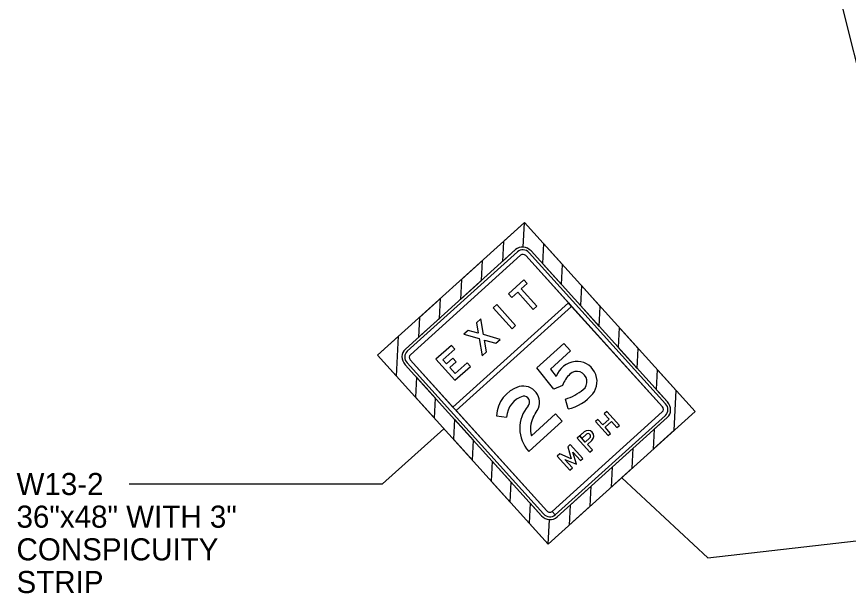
# Model space of a CAD drawing. Extents: x 571683 to 574814, y 1530838 to 1532905.
# Drawn here: x 572370 to 573075, y 1531892 to 1532381 of the extents above; entities that cross this region are included whole.
import ezdxf

# ---------------------------------------------------------------- set-up
doc = ezdxf.new("R2010")
doc.units = 0
for name, color, linetype in [('SignDetail', 7, 'Continuous'), ('SignPanel', 7, 'Continuous'), ('TextLabel', 7, 'Continuous')]:
    doc.layers.add(name, color=color, linetype=linetype)

msp = doc.modelspace()

# ---------------------------------------------------------------- linework, layer by layer
at = {"layer": 'SignDetail'}
for p, q in [((573132.85, 1532137.75), (572992.32, 1532700.81)), ((572465, 1531984.47), (572680, 1531984.47)), ((572955.73, 1531921.8), (573341.41, 1531966.12))]:
    msp.add_line(p, q, dxfattribs=at)
at = {"layer": 'SignPanel'}
for p, q in [((572792.72, 1532183.38), (572699.24, 1532098.9)), ((572794.33, 1532181.6), (572700.85, 1532097.12)), ((572794.33, 1532181.6), (572700.85, 1532097.12)), ((572794.33, 1532181.6), (572700.85, 1532097.12)), ((572794.33, 1532181.6), (572700.85, 1532097.12)), ((572797.01, 1532178.63), (572703.53, 1532094.15)), ((572797.01, 1532178.63), (572703.53, 1532094.15)), ((572797.01, 1532178.63), (572703.53, 1532094.15)), ((572703.53, 1532094.15), (572797.01, 1532178.63)), ((572920.02, 1532052.6), (572804.16, 1532180.78)), ((572920.02, 1532052.6), (572804.16, 1532180.78)), ((572920.02, 1532052.6), (572804.16, 1532180.78)), ((572920.02, 1532052.6), (572804.16, 1532180.78)), ((572921.68, 1532054.1), (572805.83, 1532182.29)), ((572917.23, 1532050.08), (572801.38, 1532178.27)), ((572917.23, 1532050.08), (572801.38, 1532178.27)), ((572917.23, 1532050.08), (572801.38, 1532178.27)), ((572801.38, 1532178.27), (572837.59, 1532138.21)), ((572837.59, 1532138.21), (572739.66, 1532049.7)), ((572837.59, 1532138.21), (572739.66, 1532049.7)), ((572837.59, 1532138.21), (572739.66, 1532049.7)), ((572837.59, 1532138.21), (572739.66, 1532049.7)), ((572840.27, 1532135.24), (572837.59, 1532138.21)), ((572840.27, 1532135.24), (572837.59, 1532138.21)), ((572840.27, 1532135.24), (572837.59, 1532138.21)), ((572840.27, 1532135.24), (572837.59, 1532138.21)), ((572837.59, 1532138.21), (572840.27, 1532135.24)), ((572742.34, 1532046.74), (572840.27, 1532135.24)), ((572742.34, 1532046.74), (572840.27, 1532135.24)), ((572742.34, 1532046.74), (572840.27, 1532135.24)), ((572742.34, 1532046.74), (572840.27, 1532135.24)), ((572840.27, 1532135.24), (572917.23, 1532050.08)), ((572693.42, 1532109.81), (572675.62, 1532093.72)), ((572700.67, 1532087.25), (572816.53, 1531959.06)), ((572700.67, 1532087.25), (572816.53, 1531959.06)), ((572700.67, 1532087.25), (572816.53, 1531959.06)), ((572700.67, 1532087.25), (572816.53, 1531959.06)), ((572703.45, 1532089.76), (572819.31, 1531961.58)), ((572703.45, 1532089.76), (572819.31, 1531961.58)), ((572703.45, 1532089.76), (572819.31, 1531961.58)), ((572739.66, 1532049.7), (572703.45, 1532089.76)), ((572699, 1532085.74), (572814.86, 1531957.55)), ((572827.12, 1532075.72), (572827.12, 1532075.72)), ((572837.21, 1532048.12), (572835.02, 1532056.58)), ((572837.21, 1532048.12), (572835.02, 1532056.58)), ((572835.02, 1532056.58), (572835.02, 1532056.58)), ((572837.21, 1532048.12), (572835.02, 1532056.58)), ((572835.02, 1532056.58), (572835.02, 1532056.58)), ((572739.66, 1532049.7), (572742.34, 1532046.74)), ((572739.66, 1532049.7), (572742.34, 1532046.74)), ((572739.66, 1532049.7), (572742.34, 1532046.74)), ((572739.66, 1532049.7), (572742.34, 1532046.74)), ((572742.34, 1532046.74), (572739.66, 1532049.7)), ((572819.31, 1531961.58), (572742.34, 1532046.74)), ((572823.68, 1531961.21), (572917.15, 1532045.7)), ((572823.7, 1531961.24), (572917.15, 1532045.7)), ((572823.7, 1531961.24), (572917.15, 1532045.7)), ((572917.15, 1532045.7), (572823.7, 1531961.24)), ((572776.48, 1532042.34), (572785.11, 1532041.3)), ((572776.48, 1532042.34), (572785.11, 1532041.3)), ((572776.48, 1532042.34), (572785.11, 1532041.3)), ((572826.36, 1531958.25), (572919.84, 1532042.73)), ((572826.39, 1531958.27), (572919.84, 1532042.73)), ((572826.39, 1531958.27), (572919.84, 1532042.73)), ((572826.39, 1531958.27), (572919.84, 1532042.73)), ((572827.97, 1531956.47), (572921.44, 1532040.95)), ((572680, 1531984.47), (572731.94, 1532031.4)), ((572855.69, 1532023.56), (572851.83, 1532020.08)), ((572853.71, 1532018), (572857.55, 1532021.48)), ((572882.75, 1531989.8), (572955.73, 1531921.8)), ((572826.36, 1531958.25), (572823.68, 1531961.21)), ((572826.36, 1531958.25), (572823.68, 1531961.21)), ((572826.36, 1531958.25), (572823.68, 1531961.21)), ((572823.7, 1531961.24), (572826.39, 1531958.27)), ((572823.7, 1531961.24), (572826.39, 1531958.27)), ((572823.7, 1531961.24), (572826.39, 1531958.27))]:
    msp.add_line(p, q, dxfattribs=at)
for points in [[(572820.44, 1531933.48), (572945.07, 1532046.13), (572800.25, 1532206.36), (572675.62, 1532093.72), (572820.44, 1531933.48)], [(572799.2, 1532185.57), (572800.25, 1532206.36), (572782.45, 1532190.27), (572781.59, 1532173.32), (572792.72, 1532183.38)], [(572815.49, 1532171.61), (572831.58, 1532153.8), (572832.44, 1532170.75), (572816.34, 1532188.56), (572815.49, 1532171.61)], [(572699.24, 1532098.9), (572792.72, 1532183.38)], [(572805.83, 1532182.29), (572921.68, 1532054.1)], [(572745.98, 1532141.14), (572763.78, 1532157.23), (572764.64, 1532174.18), (572746.84, 1532158.08), (572745.98, 1532141.14)], [(572863.76, 1532118.19), (572864.62, 1532135.14), (572848.53, 1532152.95), (572847.67, 1532136), (572863.76, 1532118.19)], [(572710.37, 1532108.95), (572728.17, 1532125.04), (572729.03, 1532141.99), (572711.22, 1532125.9), (572710.37, 1532108.95)], [(572895.95, 1532082.58), (572896.81, 1532099.53), (572880.71, 1532117.33), (572879.86, 1532100.39), (572895.95, 1532082.58)], [(572693.42, 1532109.81), (572675.62, 1532093.72), (572691.71, 1532075.92), (572693.42, 1532109.81)], [(572832.62, 1532068.15), (572825.06, 1532064.87), (572810.91, 1532083.09), (572833.74, 1532103.73), (572839.38, 1532097.5), (572822.23, 1532082.01), (572827.12, 1532075.72)], [(572832.62, 1532068.15), (572825.06, 1532064.87), (572810.91, 1532083.09), (572833.74, 1532103.73), (572839.38, 1532097.5), (572822.23, 1532082.01), (572827.12, 1532075.72)], [(572832.62, 1532068.15), (572825.06, 1532064.87), (572810.91, 1532083.09), (572833.74, 1532103.73), (572839.38, 1532097.5), (572822.23, 1532082.01), (572827.12, 1532075.72)], [(572814.86, 1531957.55), (572699, 1532085.74)], [(572921.44, 1532040.95), (572910.33, 1532030.9), (572909.47, 1532013.95), (572927.28, 1532030.05), (572928.99, 1532063.92), (572912.9, 1532081.72), (572912.04, 1532064.77)], [(572707.8, 1532058.11), (572723.89, 1532040.31), (572724.75, 1532057.26), (572708.65, 1532075.06), (572707.8, 1532058.11)], [(572912.04, 1532064.77), (572921.68, 1532054.1)], [(572756.93, 1532021.65), (572740.84, 1532039.45), (572739.98, 1532022.5), (572756.08, 1532004.7), (572756.93, 1532021.65)], [(572803.87, 1532012.04), (572832.28, 1532037.71), (572826.65, 1532043.95), (572806.12, 1532025.39)], [(572803.87, 1532012.04), (572832.28, 1532037.71), (572826.65, 1532043.95), (572806.12, 1532025.39)], [(572803.87, 1532012.04), (572832.28, 1532037.71), (572826.65, 1532043.95), (572806.12, 1532025.39)], [(572921.44, 1532040.95), (572827.97, 1531956.47), (572827.97, 1531956.47)], [(572850.98, 1532028.75), (572845.09, 1532023.42), (572855.82, 1532011.55), (572857.87, 1532013.4), (572853.71, 1532018)], [(572847.14, 1532025.27), (572845.09, 1532023.42), (572855.82, 1532011.55), (572857.87, 1532013.4), (572853.71, 1532018), (572857.55, 1532021.48)], [(572847.14, 1532025.27), (572845.09, 1532023.42), (572855.82, 1532011.55), (572857.87, 1532013.4), (572853.71, 1532018), (572857.55, 1532021.48)], [(572850.98, 1532028.75), (572847.14, 1532025.27), (572849.02, 1532023.2), (572852.87, 1532026.68)], [(572850.98, 1532028.75), (572847.14, 1532025.27), (572849.02, 1532023.2), (572852.87, 1532026.68)], [(572855.69, 1532023.56), (572851.83, 1532020.08), (572847.14, 1532025.27)], [(572855.69, 1532023.56), (572851.83, 1532020.08), (572847.14, 1532025.27)], [(572851.83, 1532020.08), (572849.02, 1532023.2), (572852.87, 1532026.68)], [(572891.67, 1531997.86), (572892.52, 1532014.81), (572874.72, 1531998.72), (572873.86, 1531981.77), (572891.67, 1531997.86)], [(572789.12, 1531986.03), (572773.02, 1532003.84), (572772.17, 1531986.89), (572788.26, 1531969.09), (572789.12, 1531986.03)], [(572856.06, 1531965.68), (572856.91, 1531982.63), (572839.11, 1531966.53), (572838.25, 1531949.59), (572856.06, 1531965.68)], [(572814.86, 1531957.55), (572805.21, 1531968.23), (572804.35, 1531951.28), (572820.44, 1531933.47), (572821.5, 1531954.28)]]:
    msp.add_lwpolyline(points, dxfattribs=at)
for points in [[(572789.53, 1532142.75), (572794.53, 1532147.27), (572807.8, 1532132.58), (572810.87, 1532135.35), (572797.6, 1532150.04), (572802.59, 1532154.56), (572799.78, 1532157.67), (572786.71, 1532145.87)], [(572789.53, 1532142.75), (572794.53, 1532147.27), (572807.8, 1532132.58), (572810.87, 1532135.35), (572797.6, 1532150.04), (572802.59, 1532154.56), (572799.78, 1532157.67), (572786.71, 1532145.87)], [(572789.53, 1532142.75), (572794.53, 1532147.27), (572807.8, 1532132.58), (572810.87, 1532135.35), (572797.6, 1532150.04), (572802.59, 1532154.56), (572799.78, 1532157.67), (572786.71, 1532145.87)], [(572789.73, 1532116.24), (572773.64, 1532134.05), (572776.71, 1532136.82), (572792.8, 1532119.02)], [(572789.73, 1532116.24), (572773.64, 1532134.05), (572776.71, 1532136.82), (572792.8, 1532119.02)], [(572789.73, 1532116.24), (572773.64, 1532134.05), (572776.71, 1532136.82), (572792.8, 1532119.02)], [(572764.38, 1532093.33), (572768.02, 1532096.63), (572766.27, 1532106.67), (572776.08, 1532103.91), (572779.73, 1532107.2), (572765.47, 1532111.21), (572763.14, 1532124.56), (572759.5, 1532121.27), (572761.04, 1532112.46), (572752.42, 1532114.88), (572748.78, 1532111.59), (572761.83, 1532107.92)], [(572764.38, 1532093.33), (572768.02, 1532096.63), (572766.27, 1532106.67), (572776.08, 1532103.91), (572779.73, 1532107.2), (572765.47, 1532111.21), (572763.14, 1532124.56), (572759.5, 1532121.27), (572761.04, 1532112.46), (572752.42, 1532114.88), (572748.78, 1532111.59), (572761.83, 1532107.92)], [(572764.38, 1532093.33), (572768.02, 1532096.63), (572766.27, 1532106.67), (572776.08, 1532103.91), (572779.73, 1532107.2), (572765.47, 1532111.21), (572763.14, 1532124.56), (572759.5, 1532121.27), (572761.04, 1532112.46), (572752.42, 1532114.88), (572748.78, 1532111.59), (572761.83, 1532107.92)], [(572751.56, 1532087.41), (572741.56, 1532078.37), (572737.07, 1532083.34), (572742.37, 1532088.13), (572739.56, 1532091.25), (572734.26, 1532086.46), (572731.1, 1532089.95), (572741.1, 1532098.98), (572738.28, 1532102.1), (572725.22, 1532090.29), (572741.31, 1532072.48), (572754.38, 1532084.29)], [(572751.56, 1532087.41), (572741.56, 1532078.37), (572737.07, 1532083.34), (572742.37, 1532088.13), (572739.56, 1532091.25), (572734.26, 1532086.46), (572731.1, 1532089.95), (572741.1, 1532098.98), (572738.28, 1532102.1), (572725.22, 1532090.29), (572741.31, 1532072.48), (572754.38, 1532084.29)], [(572751.56, 1532087.41), (572741.56, 1532078.37), (572737.07, 1532083.34), (572742.37, 1532088.13), (572739.56, 1532091.25), (572734.26, 1532086.46), (572731.1, 1532089.95), (572741.1, 1532098.98), (572738.28, 1532102.1), (572725.22, 1532090.29), (572741.31, 1532072.48), (572754.38, 1532084.29)], [(572872.21, 1532039.5), (572866.83, 1532034.64), (572862.63, 1532039.28), (572860.59, 1532037.43), (572871.32, 1532025.56), (572873.36, 1532027.41), (572868.7, 1532032.56), (572874.08, 1532037.42), (572878.74, 1532032.27), (572880.79, 1532034.12), (572870.06, 1532045.99), (572868.01, 1532044.14)], [(572872.21, 1532039.5), (572866.83, 1532034.64), (572862.63, 1532039.28), (572860.59, 1532037.43), (572871.32, 1532025.56), (572873.36, 1532027.41), (572868.7, 1532032.56), (572874.08, 1532037.42), (572878.74, 1532032.27), (572880.79, 1532034.12), (572870.06, 1532045.99), (572868.01, 1532044.14)], [(572872.21, 1532039.5), (572866.83, 1532034.64), (572862.63, 1532039.28), (572860.59, 1532037.43), (572871.32, 1532025.56), (572873.36, 1532027.41), (572868.7, 1532032.56), (572874.08, 1532037.42), (572878.74, 1532032.27), (572880.79, 1532034.12), (572870.06, 1532045.99), (572868.01, 1532044.14)], [(572834.45, 1532005.23), (572844.33, 1532001.17), (572841.29, 1532011.41), (572847.75, 1532004.26), (572849.8, 1532006.11), (572839.07, 1532017.98), (572837.01, 1532016.11), (572840.03, 1532005.93), (572830.2, 1532009.97), (572828.14, 1532008.1), (572838.87, 1531996.23), (572840.91, 1531998.08)], [(572834.45, 1532005.23), (572844.33, 1532001.17), (572841.29, 1532011.41), (572847.75, 1532004.26), (572849.8, 1532006.11), (572839.07, 1532017.98), (572837.01, 1532016.11), (572840.03, 1532005.93), (572830.2, 1532009.97), (572828.14, 1532008.1), (572838.87, 1531996.23), (572840.91, 1531998.08)], [(572834.45, 1532005.23), (572844.33, 1532001.17), (572841.29, 1532011.41), (572847.75, 1532004.26), (572849.8, 1532006.11), (572839.07, 1532017.98), (572837.01, 1532016.11), (572840.03, 1532005.93), (572830.2, 1532009.97), (572828.14, 1532008.1), (572838.87, 1531996.23), (572840.91, 1531998.08)]]:
    msp.add_lwpolyline(points, close=True, dxfattribs=at)
for centre, major_axis, ratio, start_param, end_param in [((572799.15, 1532176.26), (-6.44, 7.12), 0.937555, 4.712389, 6.283185), ((572799.15, 1532176.26), (-6.44, 7.12), 0.937555, 4.712389, 6.283185), ((572799.15, 1532176.26), (-6.44, 7.12), 0.937555, 5.51114, 6.283185), ((572799.15, 1532176.26), (-4.83, 5.34), 0.937555, 4.712389, 6.283185), ((572799.15, 1532176.26), (-4.83, 5.34), 0.937555, 4.712389, 6.283185), ((572799.15, 1532176.26), (-4.83, 5.34), 0.937555, 4.712389, 6.283185), ((572799.15, 1532176.26), (-4.83, 5.34), 0.937555, 4.712389, 6.283185), ((572799.15, 1532176.26), (-2.15, 2.37), 0.937555, 4.712389, 6.283185), ((572799.15, 1532176.26), (-2.15, 2.37), 0.937555, 4.712389, 6.283185), ((572799.15, 1532176.26), (-2.15, 2.37), 0.937555, 4.712389, 6.283185), ((572799.15, 1532176.26), (-2.15, 2.37), 0.937555, 4.712389, 6.283185), ((572705.68, 1532091.78), (-6.44, 7.12), 0.937555, 0, 1.570796), ((572705.68, 1532091.78), (-6.44, 7.12), 0.937555, 0, 1.570796), ((572705.68, 1532091.78), (-4.83, 5.34), 0.937555, 0, 1.570796), ((572705.68, 1532091.78), (-4.83, 5.34), 0.937555, 0, 1.570796), ((572705.68, 1532091.78), (-4.83, 5.34), 0.937555, 0, 1.570796), ((572705.68, 1532091.78), (-4.83, 5.34), 0.937555, 0, 1.570796), ((572705.68, 1532091.78), (-2.15, 2.37), 0.937555, 0, 1.570796), ((572705.68, 1532091.78), (-2.15, 2.37), 0.937555, 0, 1.570796), ((572705.68, 1532091.78), (-2.15, 2.37), 0.937555, 0, 1.570796), ((572705.68, 1532091.78), (-2.15, 2.37), 0.937555, 0, 1.570796), ((572845.85, 1532068.72), (-13.45, 14.88), 0.985, 5.674797, 6.76791), ((572845.85, 1532068.72), (-13.45, 14.88), 0.985, 5.674797, 6.76791), ((572845.85, 1532068.72), (-13.45, 14.88), 0.985, 5.674797, 6.76791), ((572844.97, 1532071.68), (-11.4, 12.62), 0.985, 3.29706, 5.646286), ((572844.97, 1532071.68), (-11.4, 12.62), 0.985, 3.29706, 5.646286), ((572844.97, 1532071.68), (-11.4, 12.62), 0.985, 3.29706, 5.646286), ((572844.8, 1532071.44), (-5.78, 6.39), 0.985, 3.050128, 6.31212), ((572844.8, 1532071.44), (-5.78, 6.39), 0.985, 3.050128, 6.31212), ((572844.8, 1532071.44), (-5.78, 6.39), 0.985, 3.050128, 6.31212), ((572856.17, 1532059.3), (-16.92, 18.72), 0.985, 0.021733, 0.482857), ((572856.17, 1532059.3), (-16.92, 18.72), 0.985, 0.021733, 0.482857), ((572856.17, 1532059.3), (-16.92, 18.72), 0.985, 0.021733, 0.482857), ((572804.71, 1532040.14), (-19.12, 21.16), 0.985, 5.861869, 7.048709), ((572804.71, 1532040.14), (-19.12, 21.16), 0.985, 5.861869, 7.048709), ((572804.71, 1532040.14), (-19.12, 21.16), 0.985, 5.861869, 7.048709), ((572799.39, 1532053.96), (-9.2, 10.18), 0.985, 3.445077, 5.80948), ((572799.39, 1532053.96), (-9.2, 10.18), 0.985, 3.445077, 5.80948), ((572799.39, 1532053.96), (-9.2, 10.18), 0.985, 3.445077, 5.80948), ((572804.84, 1532039.84), (-13.36, 14.78), 0.985, 5.833638, 7.052577), ((572804.84, 1532039.84), (-13.36, 14.78), 0.985, 5.833638, 7.052577), ((572804.84, 1532039.84), (-13.36, 14.78), 0.985, 5.833638, 7.052577), ((572799.94, 1532054.14), (-3.23, 3.58), 0.985, 3.193411, 5.709913), ((572799.94, 1532054.14), (-3.23, 3.58), 0.985, 3.193411, 5.709913), ((572799.94, 1532054.14), (-3.23, 3.58), 0.985, 3.193411, 5.709913), ((572822.39, 1532097.65), (-28.89, 31.97), 0.985, 2.699218, 3.100889), ((572822.39, 1532097.65), (-28.89, 31.97), 0.985, 2.699218, 3.100889), ((572822.39, 1532097.65), (-28.89, 31.97), 0.985, 2.699218, 3.100889), ((572828.72, 1532085.13), (-25.55, 28.27), 0.985, 2.625811, 3.292278), ((572828.72, 1532085.13), (-25.55, 28.27), 0.985, 2.625811, 3.292278), ((572828.72, 1532085.13), (-25.55, 28.27), 0.985, 2.625811, 3.292278), ((572915.01, 1532048.07), (-4.83, 5.34), 0.937555, 3.141593, 4.712389), ((572915.01, 1532048.07), (-4.83, 5.34), 0.937555, 3.141593, 4.712389), ((572915.01, 1532048.07), (-4.83, 5.34), 0.937555, 3.141593, 4.712389), ((572915.01, 1532048.07), (-4.83, 5.34), 0.937555, 3.141593, 4.712389), ((572915.01, 1532048.07), (-6.44, 7.12), 0.937555, 3.141593, 4.712389), ((572915.01, 1532048.07), (-6.44, 7.12), 0.937555, 3.141593, 4.712389), ((572915.01, 1532048.07), (-6.44, 7.12), 0.937555, 3.141593, 4.712389), ((572825.61, 1532031.35), (-19.79, 21.9), 0.985, 0.121378, 1.562513), ((572825.61, 1532031.35), (-19.79, 21.9), 0.985, 0.121378, 1.562513), ((572825.61, 1532031.35), (-19.79, 21.9), 0.985, 0.121378, 1.562513), ((572673.45, 1532124.62), (-106.18, 117.48), 0.985, 3.423454, 3.46857), ((572673.45, 1532124.62), (-106.18, 117.48), 0.985, 3.423454, 3.46857), ((572673.45, 1532124.62), (-106.18, 117.48), 0.985, 3.423454, 3.46857), ((572915.01, 1532048.07), (-2.15, 2.37), 0.937555, 3.141593, 4.712389), ((572915.01, 1532048.07), (-2.15, 2.37), 0.937555, 3.141593, 4.712389), ((572915.01, 1532048.07), (-2.15, 2.37), 0.937555, 3.141593, 4.712389), ((572915.01, 1532048.07), (-2.15, 2.37), 0.937555, 3.141593, 4.712389), ((572826.56, 1532030.91), (-14.37, 15.9), 0.985, 0.357174, 1.105945), ((572826.56, 1532030.91), (-14.37, 15.9), 0.985, 0.357174, 1.105945), ((572826.56, 1532030.91), (-14.37, 15.9), 0.985, 0.357174, 1.105945), ((572854.27, 1532025.11), (-3.29, 3.63), 0.985, 3.141593, 6.283185), ((572854.27, 1532025.11), (-3.29, 3.63), 0.985, 3.141593, 6.283185), ((572854.27, 1532025.11), (-3.29, 3.63), 0.985, 3.141593, 6.283185), ((572854.28, 1532025.12), (-1.41, 1.56), 0.985, 3.141593, 6.283185), ((572854.28, 1532025.12), (-1.41, 1.56), 0.985, 3.141593, 6.283185), ((572854.28, 1532025.12), (-1.41, 1.56), 0.985, 3.141593, 6.283185), ((572821.53, 1531963.59), (-2.15, 2.37), 0.937555, 1.570796, 3.141593), ((572821.53, 1531963.59), (-2.15, 2.37), 0.937555, 1.570796, 3.141593), ((572821.53, 1531963.59), (-2.15, 2.37), 0.937555, 1.570796, 3.141593), ((572821.53, 1531963.59), (-2.15, 2.37), 0.937555, 1.570796, 3.141593), ((572821.53, 1531963.59), (-6.44, 7.12), 0.937555, 1.570796, 2.370551), ((572821.53, 1531963.59), (-6.44, 7.12), 0.937555, 1.570796, 3.141593), ((572821.53, 1531963.59), (-6.44, 7.12), 0.937555, 1.570796, 3.141593), ((572821.53, 1531963.59), (-4.83, 5.34), 0.937555, 1.570796, 3.141593), ((572821.53, 1531963.59), (-4.83, 5.34), 0.937555, 1.570796, 3.141593), ((572821.53, 1531963.59), (-4.83, 5.34), 0.937555, 1.570796, 3.141593), ((572821.53, 1531963.59), (-4.83, 5.34), 0.937555, 1.570796, 3.141593)]:
    msp.add_ellipse(centre, major_axis=major_axis, ratio=ratio, start_param=start_param, end_param=end_param, dxfattribs=at)

# ---------------------------------------------------------------- texts
at = {"layer": 'TextLabel'}
for s, p in [('W13-2', (572369.44, 1531975.1)), ('36"x48" WITH 3"', (572369.44, 1531947.36)), ('CONSPICUITY', (572369.44, 1531919.62)), ('STRIP', (572369.44, 1531891.88))]:
    msp.add_text(s, height=18.74, dxfattribs=at).set_placement(p)

doc.saveas('drawing.dxf')
